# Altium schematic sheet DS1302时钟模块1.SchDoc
size A4
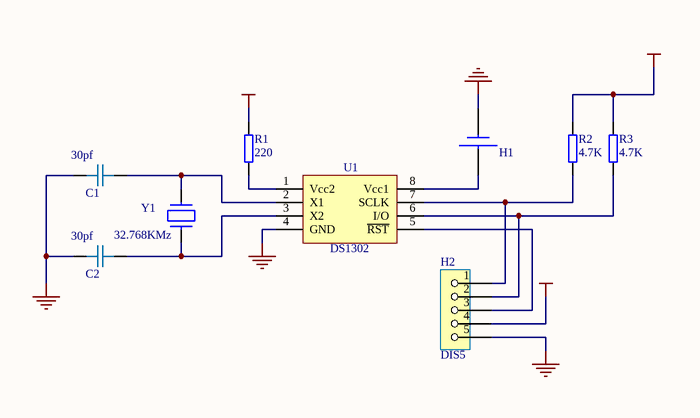
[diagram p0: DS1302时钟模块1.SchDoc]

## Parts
C1  30pf  [PCBComponent_1]
C2  30pf  [PCBComponent_1]
H1  BETT  [BETT]  (value not drawn)
H2  DIS5  [DIS5]
R1  220  [PCBComponent_1]
R2  4.7K  [PCBComponent_1]
R3  4.7K  [PCBComponent_1]
U1  DS1302  [DIP8]
Y1  32.768kMZ  [32.768MH]

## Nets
GND: C1.2 C2.1 H1.2 H2.5 U1.4(GND)
VCC: H2.4 R1.2 R2.2 R3.2
NetC1_1: C1.1 U1.2(X1) Y1.2
NetC2_2: C2.2 U1.3(X2) Y1.1
NetH1_1: H1.1 U1.8(Vcc1)
NetH2_1: H2.1 R2.1 U1.7(SCLK)
NetH2_2: H2.2 R3.1 U1.6(I/O)
NetH2_3: H2.3 U1.5(~{RST})
NetR1_1: R1.1 U1.1(Vcc2)

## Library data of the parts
C1 C2 = C_1
R1-R3 = RESIS
Y1 = XTAL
